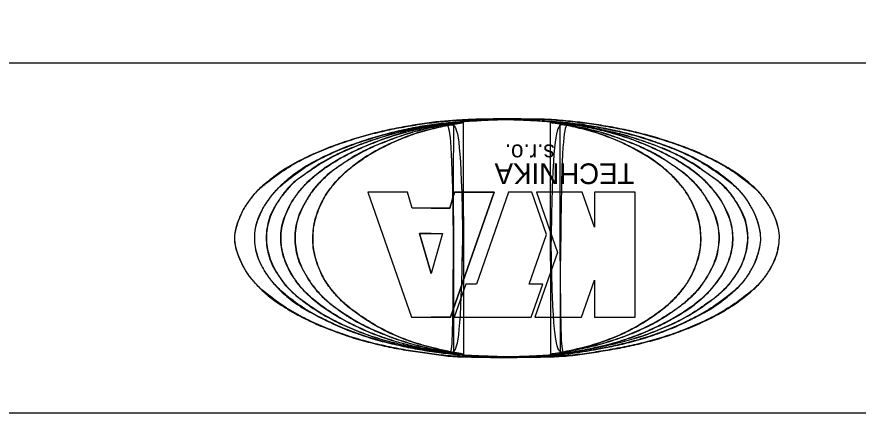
# Model space of a CAD drawing. Extents: x -728472.2 to -728419.7, y -1073099.3 to -1073025.
# Drawn here: x -728464.08 to -728452.08, y -1073060.53 to -1073054.87 of the extents above; entities that cross this region are included whole.
import ezdxf

# ---------------------------------------------------------------- set-up
doc = ezdxf.new("R2010")
doc.units = 0
doc.layers.add('_popis', color=7, linetype='Continuous')
doc.layers.add('Rozpiska_pole_6', color=7, linetype='Continuous')

msp = doc.modelspace()

# ---------------------------------------------------------------- linework, layer by layer
at = {"layer": '_popis'}
for p, q in [((-728458.343, -1073057.961), (-728458.177, -1073057.961)), ((-728458.177, -1073058.535), (-728458.343, -1073057.961))]:
    msp.add_line(p, q, dxfattribs=at)
for points in [[(-728458.177, -1073057.599), (-728458.448, -1073057.599), (-728458.514, -1073057.371), (-728459.077, -1073057.371), (-728458.456, -1073059.156), (-728458.177, -1073059.156)], [(-728458.177, -1073057.599), (-728458.448, -1073057.599), (-728458.514, -1073057.371), (-728459.077, -1073057.371), (-728458.456, -1073059.156), (-728458.177, -1073059.156)], [(-728458.177, -1073057.599), (-728457.907, -1073057.599), (-728457.841, -1073057.371), (-728457.278, -1073057.371), (-728457.899, -1073059.156), (-728458.177, -1073059.156)], [(-728458.177, -1073059.156), (-728457.899, -1073059.156), (-728457.278, -1073057.371), (-728457.841, -1073057.371), (-728457.907, -1073057.599), (-728458.177, -1073057.599)], [(-728456.748, -1073059.156), (-728456.583, -1073058.684), (-728456.777, -1073058.684), (-728456.53, -1073057.975), (-728456.74, -1073057.371), (-728457.073, -1073057.371), (-728457.53, -1073058.684), (-728457.681, -1073058.684), (-728457.845, -1073059.156), (-728456.748, -1073059.156)], [(-728456.748, -1073059.156), (-728456.583, -1073058.684), (-728456.777, -1073058.684), (-728456.53, -1073057.975), (-728456.74, -1073057.371), (-728457.073, -1073057.371), (-728457.53, -1073058.684), (-728457.681, -1073058.684), (-728457.845, -1073059.156), (-728456.748, -1073059.156)], [(-728455.263, -1073059.156), (-728455.263, -1073057.371), (-728455.847, -1073057.371), (-728455.847, -1073057.874), (-728456.022, -1073057.371), (-728456.672, -1073057.371), (-728456.373, -1073058.232), (-728456.694, -1073059.156), (-728456.032, -1073059.156), (-728455.847, -1073058.627), (-728455.847, -1073059.156), (-728455.263, -1073059.156)], [(-728455.263, -1073059.156), (-728455.263, -1073057.371), (-728455.847, -1073057.371), (-728455.847, -1073057.874), (-728456.022, -1073057.371), (-728456.672, -1073057.371), (-728456.373, -1073058.232), (-728456.694, -1073059.156), (-728456.032, -1073059.156), (-728455.847, -1073058.627), (-728455.847, -1073059.156), (-728455.263, -1073059.156)], [(-728458.177, -1073057.961), (-728458.343, -1073057.961), (-728458.177, -1073058.535)], [(-728458.177, -1073057.961), (-728458.011, -1073057.961), (-728458.177, -1073058.535)], [(-728458.177, -1073057.961), (-728458.011, -1073057.961), (-728458.177, -1073058.535)]]:
    msp.add_lwpolyline(points, dxfattribs=at)
for points in [[(-728457.095, -1073059.733), (-728456.792, -1073059.728), (-728456.559, -1073059.725), (-728456.291, -1073059.714), (-728456.023, -1073059.686), (-728455.755, -1073059.644), (-728455.486, -1073059.597), (-728455.218, -1073059.54), (-728454.95, -1073059.47), (-728454.682, -1073059.382), (-728454.414, -1073059.276), (-728454.147, -1073059.152), (-728453.879, -1073058.994), (-728453.611, -1073058.792), (-728453.507, -1073058.694), (-728453.397, -1073058.56), (-728453.316, -1073058.427), (-728453.255, -1073058.292), (-728453.223, -1073058.159), (-728453.208, -1073058.024), (-728453.222, -1073057.892), (-728453.262, -1073057.757), (-728453.323, -1073057.622), (-728453.407, -1073057.489), (-728453.515, -1073057.354), (-728453.611, -1073057.265), (-728453.879, -1073057.062), (-728454.146, -1073056.91), (-728454.412, -1073056.787), (-728454.682, -1073056.685), (-728454.951, -1073056.597), (-728455.218, -1073056.524), (-728455.484, -1073056.466), (-728455.754, -1073056.416), (-728456.022, -1073056.378), (-728456.292, -1073056.349), (-728456.557, -1073056.331), (-728456.827, -1073056.328), (-728457.095, -1073056.323), (-728457.363, -1073056.328), (-728457.632, -1073056.335), (-728457.899, -1073056.352), (-728458.166, -1073056.377), (-728458.435, -1073056.417), (-728458.703, -1073056.465), (-728458.971, -1073056.525), (-728459.24, -1073056.6), (-728459.508, -1073056.688), (-728459.775, -1073056.792), (-728460.042, -1073056.917), (-728460.312, -1073057.075), (-728460.581, -1073057.284), (-728460.661, -1073057.355), (-728460.766, -1073057.488), (-728460.855, -1073057.621), (-728460.917, -1073057.757), (-728460.96, -1073057.89), (-728460.982, -1073058.024), (-728460.966, -1073058.158), (-728460.92, -1073058.293), (-728460.859, -1073058.429), (-728460.779, -1073058.56), (-728460.666, -1073058.694), (-728460.583, -1073058.776), (-728460.312, -1073058.985), (-728460.044, -1073059.144), (-728459.778, -1073059.271), (-728459.509, -1073059.374), (-728459.239, -1073059.467), (-728458.973, -1073059.537), (-728458.703, -1073059.597), (-728458.433, -1073059.644), (-728458.164, -1073059.682), (-728457.898, -1073059.715), (-728457.631, -1073059.725), (-728457.363, -1073059.73), (-728457.095, -1073059.733), (-728457.095, -1073059.733), (-728457.095, -1073059.733)], [(-728457.095, -1073059.725), (-728457.184, -1073059.722), (-728457.363, -1073059.714), (-728457.632, -1073059.712), (-728457.899, -1073059.682), (-728458.168, -1073059.648), (-728458.436, -1073059.604), (-728458.704, -1073059.544), (-728458.974, -1073059.48), (-728459.242, -1073059.389), (-728459.512, -1073059.286), (-728459.779, -1073059.154), (-728460.058, -1073059.004), (-728460.264, -1073058.84), (-728460.416, -1073058.687), (-728460.512, -1073058.566), (-728460.595, -1073058.43), (-728460.656, -1073058.296), (-728460.688, -1073058.159), (-728460.7, -1073058.024), (-728460.69, -1073057.887), (-728460.649, -1073057.753), (-728460.589, -1073057.617), (-728460.503, -1073057.484), (-728460.412, -1073057.364), (-728460.258, -1073057.219), (-728460.058, -1073057.055), (-728459.781, -1073056.899), (-728459.511, -1073056.773), (-728459.242, -1073056.669), (-728458.972, -1073056.585), (-728458.704, -1073056.51), (-728458.435, -1073056.454), (-728458.167, -1073056.405), (-728457.899, -1073056.379), (-728457.631, -1073056.356), (-728457.363, -1073056.339), (-728457.095, -1073056.33), (-728456.826, -1073056.34), (-728456.559, -1073056.359), (-728456.29, -1073056.374), (-728456.021, -1073056.406), (-728455.753, -1073056.449), (-728455.485, -1073056.506), (-728455.215, -1073056.573), (-728454.948, -1073056.665), (-728454.677, -1073056.762), (-728454.406, -1073056.885), (-728454.136, -1073057.048), (-728453.925, -1073057.209), (-728453.763, -1073057.357), (-728453.667, -1073057.482), (-728453.587, -1073057.619), (-728453.527, -1073057.753), (-728453.49, -1073057.888), (-728453.466, -1073058.024), (-728453.487, -1073058.16), (-728453.521, -1073058.296), (-728453.578, -1073058.431), (-728453.657, -1073058.566), (-728453.754, -1073058.697), (-728453.922, -1073058.846), (-728454.133, -1073059.015), (-728454.41, -1073059.163), (-728454.677, -1073059.292), (-728454.947, -1073059.397), (-728455.216, -1073059.483), (-728455.485, -1073059.552), (-728455.714, -1073059.597), (-728455.893, -1073059.63), (-728456.072, -1073059.659), (-728456.29, -1073059.691), (-728456.559, -1073059.708), (-728456.827, -1073059.719), (-728457.005, -1073059.723), (-728457.095, -1073059.725)], [(-728457.095, -1073059.733), (-728456.994, -1073059.731), (-728456.815, -1073059.728), (-728456.547, -1073059.726), (-728456.29, -1073059.717), (-728456.022, -1073059.689), (-728455.754, -1073059.644), (-728455.485, -1073059.6), (-728455.217, -1073059.542), (-728454.948, -1073059.472), (-728454.679, -1073059.385), (-728454.411, -1073059.277), (-728454.139, -1073059.155), (-728453.869, -1073058.994), (-728453.658, -1073058.836), (-728453.497, -1073058.69), (-728453.397, -1073058.567), (-728453.315, -1073058.43), (-728453.251, -1073058.297), (-728453.222, -1073058.16), (-728453.202, -1073058.025), (-728453.218, -1073057.888), (-728453.261, -1073057.754), (-728453.321, -1073057.617), (-728453.408, -1073057.484), (-728453.502, -1073057.361), (-728453.661, -1073057.218), (-728453.866, -1073057.06), (-728454.141, -1073056.91), (-728454.409, -1073056.783), (-728454.68, -1073056.684), (-728454.949, -1073056.596), (-728455.216, -1073056.522), (-728455.484, -1073056.464), (-728455.753, -1073056.415), (-728456.022, -1073056.377), (-728456.29, -1073056.348), (-728456.558, -1073056.327), (-728456.826, -1073056.33), (-728457.095, -1073056.32), (-728457.363, -1073056.329), (-728457.568, -1073056.331), (-728457.683, -1073056.337), (-728457.709, -1073056.339)], [(-728457.709, -1073056.339), (-728457.773, -1073056.342), (-728457.925, -1073056.353), (-728458.168, -1073056.373), (-728458.435, -1073056.417), (-728458.704, -1073056.463), (-728458.973, -1073056.524), (-728459.241, -1073056.598), (-728459.51, -1073056.687), (-728459.779, -1073056.79), (-728460.049, -1073056.916), (-728460.325, -1073057.072), (-728460.521, -1073057.233), (-728460.68, -1073057.366), (-728460.764, -1073057.486), (-728460.858, -1073057.615), (-728460.918, -1073057.753), (-728460.963, -1073057.888), (-728460.989, -1073058.023), (-728460.971, -1073058.162), (-728460.919, -1073058.295), (-728460.863, -1073058.432), (-728460.779, -1073058.569), (-728460.681, -1073058.681), (-728460.53, -1073058.83), (-728460.324, -1073058.985), (-728460.051, -1073059.145), (-728459.782, -1073059.274), (-728459.51, -1073059.374), (-728459.244, -1073059.471), (-728458.973, -1073059.538), (-728458.705, -1073059.6), (-728458.434, -1073059.645), (-728458.165, -1073059.68), (-728457.899, -1073059.722), (-728457.631, -1073059.725), (-728457.363, -1073059.731), (-728457.184, -1073059.732), (-728457.095, -1073059.733)], [(-728457.095, -1073059.725), (-728456.827, -1073059.718), (-728456.559, -1073059.707), (-728456.291, -1073059.687), (-728456.023, -1073059.651), (-728455.902, -1073059.631), (-728455.755, -1073059.605), (-728455.486, -1073059.55), (-728455.218, -1073059.481), (-728454.95, -1073059.395), (-728454.682, -1073059.29), (-728454.414, -1073059.162), (-728454.147, -1073059.012), (-728453.879, -1073058.807), (-728453.759, -1073058.695), (-728453.657, -1073058.56), (-728453.58, -1073058.427), (-728453.524, -1073058.292), (-728453.489, -1073058.159), (-728453.473, -1073058.024), (-728453.491, -1073057.89), (-728453.529, -1073057.757), (-728453.588, -1073057.623), (-728453.667, -1073057.488), (-728453.772, -1073057.354), (-728453.879, -1073057.253), (-728454.147, -1073057.048), (-728454.414, -1073056.888), (-728454.681, -1073056.765), (-728454.949, -1073056.665), (-728455.218, -1073056.576), (-728455.486, -1073056.507), (-728455.754, -1073056.451), (-728456.023, -1073056.408), (-728456.29, -1073056.377), (-728456.558, -1073056.359), (-728456.827, -1073056.342), (-728457.095, -1073056.333), (-728457.363, -1073056.34), (-728457.631, -1073056.357), (-728457.898, -1073056.379), (-728458.166, -1073056.409), (-728458.435, -1073056.455), (-728458.703, -1073056.513), (-728458.97, -1073056.586), (-728459.239, -1073056.671), (-728459.507, -1073056.775), (-728459.775, -1073056.9), (-728460.044, -1073057.056), (-728460.312, -1073057.271), (-728460.397, -1073057.354), (-728460.504, -1073057.489), (-728460.587, -1073057.622), (-728460.647, -1073057.757), (-728460.685, -1073057.89), (-728460.696, -1073058.023), (-728460.685, -1073058.158), (-728460.653, -1073058.291), (-728460.594, -1073058.426), (-728460.512, -1073058.56), (-728460.406, -1073058.695), (-728460.312, -1073058.79), (-728460.044, -1073059.002), (-728459.775, -1073059.154), (-728459.507, -1073059.283), (-728459.24, -1073059.388), (-728458.971, -1073059.476), (-728458.703, -1073059.544), (-728458.435, -1073059.601), (-728458.167, -1073059.647), (-728457.899, -1073059.682), (-728457.631, -1073059.707), (-728457.364, -1073059.716), (-728457.095, -1073059.725), (-728457.095, -1073059.725), (-728457.095, -1073059.725)], [(-728457.854, -1073056.383), (-728457.905, -1073056.387), (-728458.011, -1073056.396), (-728458.205, -1073056.426), (-728458.437, -1073056.474), (-728458.708, -1073056.531), (-728458.976, -1073056.617), (-728459.245, -1073056.71), (-728459.515, -1073056.826), (-728459.789, -1073056.973), (-728459.979, -1073057.123), (-728460.148, -1073057.235), (-728460.249, -1073057.348), (-728460.351, -1073057.484), (-728460.43, -1073057.619), (-728460.492, -1073057.752), (-728460.519, -1073057.889), (-728460.534, -1073058.024), (-728460.52, -1073058.16), (-728460.489, -1073058.295), (-728460.437, -1073058.433), (-728460.353, -1073058.564), (-728460.258, -1073058.706), (-728460.148, -1073058.811), (-728459.988, -1073058.942), (-728459.786, -1073059.083), (-728459.514, -1073059.236), (-728459.243, -1073059.35), (-728458.975, -1073059.452), (-728458.705, -1073059.524), (-728458.435, -1073059.585), (-728458.167, -1073059.638), (-728457.974, -1073059.673), (-728457.869, -1073059.679), (-728457.855, -1073059.68)], [(-728457.854, -1073056.383), (-728458.008, -1073056.398), (-728458.168, -1073056.421), (-728458.436, -1073056.474), (-728458.706, -1073056.535), (-728458.975, -1073056.618), (-728459.241, -1073056.712), (-728459.508, -1073056.828), (-728459.777, -1073056.977), (-728460.047, -1073057.167), (-728460.119, -1073057.218), (-728460.25, -1073057.354), (-728460.352, -1073057.491), (-728460.429, -1073057.622), (-728460.487, -1073057.755), (-728460.518, -1073057.891), (-728460.529, -1073058.025), (-728460.518, -1073058.156), (-728460.486, -1073058.293), (-728460.433, -1073058.428), (-728460.355, -1073058.561), (-728460.259, -1073058.695), (-728460.122, -1073058.831), (-728460.048, -1073058.892), (-728459.777, -1073059.083), (-728459.506, -1073059.234), (-728459.239, -1073059.35), (-728458.975, -1073059.447), (-728458.701, -1073059.523), (-728458.435, -1073059.584), (-728458.166, -1073059.638), (-728457.897, -1073059.677), (-728457.855, -1073059.68), (-728457.854, -1073056.383), (-728457.855, -1073059.68)], [(-728457.855, -1073059.68), (-728457.952, -1073059.666), (-728458.146, -1073059.636), (-728458.43, -1073059.578), (-728458.706, -1073059.502), (-728458.977, -1073059.413), (-728459.244, -1073059.294), (-728459.515, -1073059.153), (-728459.752, -1073058.998), (-728459.938, -1073058.842), (-728460.062, -1073058.7), (-728460.159, -1073058.566), (-728460.231, -1073058.431), (-728460.283, -1073058.295), (-728460.314, -1073058.159), (-728460.323, -1073058.024), (-728460.313, -1073057.888), (-728460.279, -1073057.753), (-728460.222, -1073057.619), (-728460.151, -1073057.482), (-728460.05, -1073057.35), (-728459.928, -1073057.21), (-728459.748, -1073057.055), (-728459.515, -1073056.903), (-728459.243, -1073056.767), (-728458.974, -1073056.652), (-728458.706, -1073056.556), (-728458.437, -1073056.485), (-728458.194, -1073056.435), (-728457.999, -1073056.403), (-728457.895, -1073056.389), (-728457.854, -1073056.383)], [(-728457.855, -1073059.68), (-728458.144, -1073059.634), (-728458.435, -1073059.574), (-728458.704, -1073059.5), (-728458.973, -1073059.409), (-728459.239, -1073059.293), (-728459.507, -1073059.152), (-728459.776, -1073058.973), (-728459.944, -1073058.829), (-728460.064, -1073058.694), (-728460.158, -1073058.561), (-728460.229, -1073058.428), (-728460.281, -1073058.292), (-728460.311, -1073058.157), (-728460.32, -1073058.024), (-728460.309, -1073057.889), (-728460.277, -1073057.757), (-728460.221, -1073057.623), (-728460.149, -1073057.487), (-728460.052, -1073057.355), (-728459.932, -1073057.221), (-728459.773, -1073057.082), (-728459.508, -1073056.906), (-728459.238, -1073056.768), (-728458.971, -1073056.654), (-728458.702, -1073056.559), (-728458.436, -1073056.487), (-728458.167, -1073056.432), (-728457.976, -1073056.4), (-728457.854, -1073056.383), (-728457.855, -1073059.68), (-728457.854, -1073056.383)], [(-728457.714, -1073056.379), (-728457.776, -1073056.384), (-728457.929, -1073056.397), (-728458.168, -1073056.449), (-728458.438, -1073056.509), (-728458.705, -1073056.602), (-728458.976, -1073056.706), (-728459.25, -1073056.836), (-728459.452, -1073056.979), (-728459.631, -1073057.097), (-728459.75, -1073057.215), (-728459.872, -1073057.346), (-728459.954, -1073057.487), (-728460.031, -1073057.618), (-728460.083, -1073057.753), (-728460.112, -1073057.888), (-728460.126, -1073058.024), (-728460.11, -1073058.159), (-728460.089, -1073058.296), (-728460.034, -1073058.43), (-728459.962, -1073058.563), (-728459.875, -1073058.701), (-728459.762, -1073058.838), (-728459.633, -1073058.952), (-728459.459, -1073059.084), (-728459.248, -1073059.222), (-728458.976, -1073059.355), (-728458.707, -1073059.46), (-728458.439, -1073059.548), (-728458.169, -1073059.609), (-728457.928, -1073059.659), (-728457.776, -1073059.677), (-728457.714, -1073059.684)], [(-728457.714, -1073056.379), (-728457.899, -1073056.398), (-728458.168, -1073056.449), (-728458.434, -1073056.513), (-728458.703, -1073056.603), (-728458.972, -1073056.708), (-728459.239, -1073056.84), (-728459.507, -1073057.015), (-728459.608, -1073057.086), (-728459.754, -1073057.221), (-728459.87, -1073057.354), (-728459.955, -1073057.489), (-728460.029, -1073057.623), (-728460.08, -1073057.757), (-728460.109, -1073057.888), (-728460.121, -1073058.024), (-728460.109, -1073058.159), (-728460.084, -1073058.292), (-728460.033, -1073058.425), (-728459.961, -1073058.562), (-728459.875, -1073058.694), (-728459.764, -1073058.829), (-728459.616, -1073058.963), (-728459.506, -1073059.047), (-728459.239, -1073059.22), (-728458.972, -1073059.352), (-728458.703, -1073059.459), (-728458.436, -1073059.544), (-728458.168, -1073059.609), (-728457.899, -1073059.66), (-728457.714, -1073059.684), (-728457.714, -1073056.379), (-728457.714, -1073059.684)], [(-728457.714, -1073059.684), (-728457.776, -1073059.675), (-728457.928, -1073059.653), (-728458.168, -1073059.593), (-728458.439, -1073059.521), (-728458.71, -1073059.416), (-728458.979, -1073059.277), (-728459.216, -1073059.123), (-728459.409, -1073058.974), (-728459.544, -1073058.834), (-728459.651, -1073058.7), (-728459.732, -1073058.565), (-728459.79, -1073058.429), (-728459.833, -1073058.294), (-728459.861, -1073058.16), (-728459.865, -1073058.024), (-728459.857, -1073057.889), (-728459.831, -1073057.754), (-728459.783, -1073057.62), (-728459.724, -1073057.484), (-728459.64, -1073057.35), (-728459.533, -1073057.214), (-728459.398, -1073057.081), (-728459.214, -1073056.928), (-728458.98, -1073056.782), (-728458.709, -1073056.648), (-728458.44, -1073056.538), (-728458.169, -1073056.463), (-728457.927, -1073056.413), (-728457.776, -1073056.389), (-728457.714, -1073056.379)], [(-728457.714, -1073059.684), (-728457.899, -1073059.654), (-728458.166, -1073059.593), (-728458.436, -1073059.517), (-728458.703, -1073059.413), (-728458.972, -1073059.275), (-728459.239, -1073059.101), (-728459.415, -1073058.961), (-728459.545, -1073058.828), (-728459.651, -1073058.694), (-728459.73, -1073058.561), (-728459.788, -1073058.426), (-728459.831, -1073058.292), (-728459.857, -1073058.158), (-728459.863, -1073058.025), (-728459.854, -1073057.89), (-728459.828, -1073057.756), (-728459.783, -1073057.623), (-728459.723, -1073057.489), (-728459.639, -1073057.354), (-728459.535, -1073057.223), (-728459.401, -1073057.088), (-728459.24, -1073056.954), (-728458.972, -1073056.783), (-728458.704, -1073056.65), (-728458.436, -1073056.543), (-728458.165, -1073056.465), (-728457.899, -1073056.41), (-728457.714, -1073056.379), (-728457.714, -1073059.684), (-728457.714, -1073056.379)], [(-728456.475, -1073056.379), (-728456.414, -1073056.384), (-728456.261, -1073056.397), (-728456.022, -1073056.449), (-728455.751, -1073056.509), (-728455.484, -1073056.602), (-728455.214, -1073056.706), (-728454.94, -1073056.836), (-728454.738, -1073056.979), (-728454.558, -1073057.097), (-728454.44, -1073057.215), (-728454.318, -1073057.346), (-728454.235, -1073057.487), (-728454.158, -1073057.618), (-728454.106, -1073057.753), (-728454.078, -1073057.888), (-728454.063, -1073058.024), (-728454.079, -1073058.159), (-728454.1, -1073058.296), (-728454.156, -1073058.43), (-728454.228, -1073058.563), (-728454.315, -1073058.701), (-728454.428, -1073058.838), (-728454.556, -1073058.952), (-728454.731, -1073059.084), (-728454.942, -1073059.222), (-728455.213, -1073059.355), (-728455.483, -1073059.46), (-728455.751, -1073059.548), (-728456.021, -1073059.609), (-728456.261, -1073059.659), (-728456.414, -1073059.677), (-728456.475, -1073059.684)], [(-728456.475, -1073059.684), (-728456.414, -1073059.675), (-728456.261, -1073059.653), (-728456.021, -1073059.593), (-728455.75, -1073059.521), (-728455.48, -1073059.416), (-728455.21, -1073059.277), (-728454.974, -1073059.123), (-728454.781, -1073058.974), (-728454.645, -1073058.834), (-728454.539, -1073058.7), (-728454.458, -1073058.565), (-728454.4, -1073058.429), (-728454.356, -1073058.294), (-728454.328, -1073058.16), (-728454.324, -1073058.024), (-728454.332, -1073057.889), (-728454.358, -1073057.754), (-728454.406, -1073057.62), (-728454.465, -1073057.484), (-728454.55, -1073057.35), (-728454.656, -1073057.214), (-728454.792, -1073057.081), (-728454.976, -1073056.928), (-728455.21, -1073056.782), (-728455.481, -1073056.648), (-728455.75, -1073056.538), (-728456.02, -1073056.463), (-728456.262, -1073056.413), (-728456.414, -1073056.389), (-728456.475, -1073056.379)], [(-728456.475, -1073056.379), (-728456.291, -1073056.398), (-728456.021, -1073056.449), (-728455.756, -1073056.513), (-728455.487, -1073056.603), (-728455.218, -1073056.708), (-728454.951, -1073056.84), (-728454.682, -1073057.015), (-728454.581, -1073057.086), (-728454.435, -1073057.221), (-728454.32, -1073057.354), (-728454.234, -1073057.489), (-728454.16, -1073057.623), (-728454.109, -1073057.757), (-728454.08, -1073057.888), (-728454.068, -1073058.024), (-728454.08, -1073058.159), (-728454.105, -1073058.292), (-728454.156, -1073058.425), (-728454.229, -1073058.562), (-728454.314, -1073058.694), (-728454.426, -1073058.829), (-728454.573, -1073058.963), (-728454.683, -1073059.047), (-728454.951, -1073059.22), (-728455.217, -1073059.352), (-728455.487, -1073059.459), (-728455.753, -1073059.544), (-728456.021, -1073059.609), (-728456.291, -1073059.66), (-728456.475, -1073059.684), (-728456.475, -1073056.379), (-728456.475, -1073059.684)], [(-728456.475, -1073059.684), (-728456.291, -1073059.654), (-728456.023, -1073059.593), (-728455.754, -1073059.517), (-728455.486, -1073059.413), (-728455.218, -1073059.275), (-728454.95, -1073059.101), (-728454.774, -1073058.961), (-728454.644, -1073058.828), (-728454.539, -1073058.694), (-728454.46, -1073058.561), (-728454.401, -1073058.426), (-728454.358, -1073058.292), (-728454.332, -1073058.158), (-728454.326, -1073058.025), (-728454.335, -1073057.89), (-728454.361, -1073057.756), (-728454.407, -1073057.623), (-728454.467, -1073057.489), (-728454.55, -1073057.354), (-728454.654, -1073057.223), (-728454.789, -1073057.088), (-728454.95, -1073056.954), (-728455.218, -1073056.783), (-728455.486, -1073056.65), (-728455.753, -1073056.543), (-728456.024, -1073056.465), (-728456.291, -1073056.41), (-728456.475, -1073056.379), (-728456.475, -1073059.684), (-728456.475, -1073056.379)], [(-728456.334, -1073059.68), (-728456.238, -1073059.666), (-728456.043, -1073059.636), (-728455.76, -1073059.578), (-728455.483, -1073059.502), (-728455.213, -1073059.413), (-728454.945, -1073059.294), (-728454.675, -1073059.153), (-728454.438, -1073058.998), (-728454.252, -1073058.842), (-728454.128, -1073058.7), (-728454.03, -1073058.566), (-728453.958, -1073058.431), (-728453.906, -1073058.295), (-728453.875, -1073058.159), (-728453.866, -1073058.024), (-728453.876, -1073057.888), (-728453.91, -1073057.753), (-728453.968, -1073057.619), (-728454.038, -1073057.482), (-728454.139, -1073057.35), (-728454.262, -1073057.21), (-728454.441, -1073057.055), (-728454.675, -1073056.903), (-728454.947, -1073056.767), (-728455.216, -1073056.652), (-728455.483, -1073056.556), (-728455.753, -1073056.485), (-728455.996, -1073056.435), (-728456.19, -1073056.403), (-728456.295, -1073056.389), (-728456.335, -1073056.383)], [(-728456.335, -1073056.383), (-728456.284, -1073056.387), (-728456.179, -1073056.396), (-728455.984, -1073056.426), (-728455.752, -1073056.474), (-728455.481, -1073056.531), (-728455.214, -1073056.617), (-728454.945, -1073056.71), (-728454.675, -1073056.826), (-728454.401, -1073056.973), (-728454.211, -1073057.123), (-728454.041, -1073057.235), (-728453.941, -1073057.348), (-728453.839, -1073057.484), (-728453.759, -1073057.619), (-728453.697, -1073057.752), (-728453.67, -1073057.889), (-728453.655, -1073058.024), (-728453.67, -1073058.16), (-728453.701, -1073058.295), (-728453.753, -1073058.433), (-728453.836, -1073058.564), (-728453.932, -1073058.706), (-728454.042, -1073058.811), (-728454.202, -1073058.942), (-728454.404, -1073059.083), (-728454.675, -1073059.236), (-728454.947, -1073059.35), (-728455.214, -1073059.452), (-728455.484, -1073059.524), (-728455.755, -1073059.585), (-728456.022, -1073059.638), (-728456.216, -1073059.673), (-728456.32, -1073059.679), (-728456.334, -1073059.68)], [(-728456.335, -1073056.383), (-728456.182, -1073056.398), (-728456.021, -1073056.421), (-728455.753, -1073056.474), (-728455.484, -1073056.535), (-728455.215, -1073056.618), (-728454.948, -1073056.712), (-728454.681, -1073056.828), (-728454.412, -1073056.977), (-728454.143, -1073057.167), (-728454.071, -1073057.218), (-728453.939, -1073057.354), (-728453.838, -1073057.491), (-728453.76, -1073057.622), (-728453.702, -1073057.755), (-728453.672, -1073057.891), (-728453.66, -1073058.025), (-728453.672, -1073058.156), (-728453.703, -1073058.293), (-728453.756, -1073058.428), (-728453.835, -1073058.561), (-728453.931, -1073058.695), (-728454.068, -1073058.831), (-728454.141, -1073058.892), (-728454.412, -1073059.083), (-728454.683, -1073059.234), (-728454.95, -1073059.35), (-728455.215, -1073059.447), (-728455.489, -1073059.523), (-728455.754, -1073059.584), (-728456.024, -1073059.638), (-728456.292, -1073059.677), (-728456.334, -1073059.68), (-728456.335, -1073056.383), (-728456.334, -1073059.68)], [(-728456.334, -1073059.68), (-728456.045, -1073059.634), (-728455.755, -1073059.574), (-728455.485, -1073059.5), (-728455.216, -1073059.409), (-728454.951, -1073059.293), (-728454.683, -1073059.152), (-728454.414, -1073058.973), (-728454.246, -1073058.829), (-728454.126, -1073058.694), (-728454.031, -1073058.561), (-728453.96, -1073058.428), (-728453.909, -1073058.292), (-728453.879, -1073058.157), (-728453.87, -1073058.024), (-728453.88, -1073057.889), (-728453.913, -1073057.757), (-728453.968, -1073057.623), (-728454.04, -1073057.487), (-728454.138, -1073057.355), (-728454.257, -1073057.221), (-728454.416, -1073057.082), (-728454.682, -1073056.906), (-728454.951, -1073056.768), (-728455.219, -1073056.654), (-728455.487, -1073056.559), (-728455.754, -1073056.487), (-728456.023, -1073056.432), (-728456.213, -1073056.4), (-728456.335, -1073056.383), (-728456.334, -1073059.68), (-728456.335, -1073056.383)]]:
    msp.add_open_spline(points, degree=3, dxfattribs=at)
at = {"layer": 'Rozpiska_pole_6'}
msp.add_line((-728424.685, -1073055.528), (-728467.185, -1073055.528), dxfattribs=at)
msp.add_lwpolyline([(-728424.685, -1073060.528), (-728467.185, -1073060.528), (-728467.185, -1073048.028), (-728424.685, -1073048.028)], close=True, dxfattribs=at)

# ---------------------------------------------------------------- texts
at = {"layer": '_popis'}
for s, height, p in [('s.r.o.', 0.2386, (-728456.415, -1073056.691)), ('TECHNIKA', 0.2949, (-728455.276, -1073056.961))]:
    msp.add_text(s, height=height, rotation=180, dxfattribs=at).set_placement(p)

doc.saveas('drawing.dxf')
